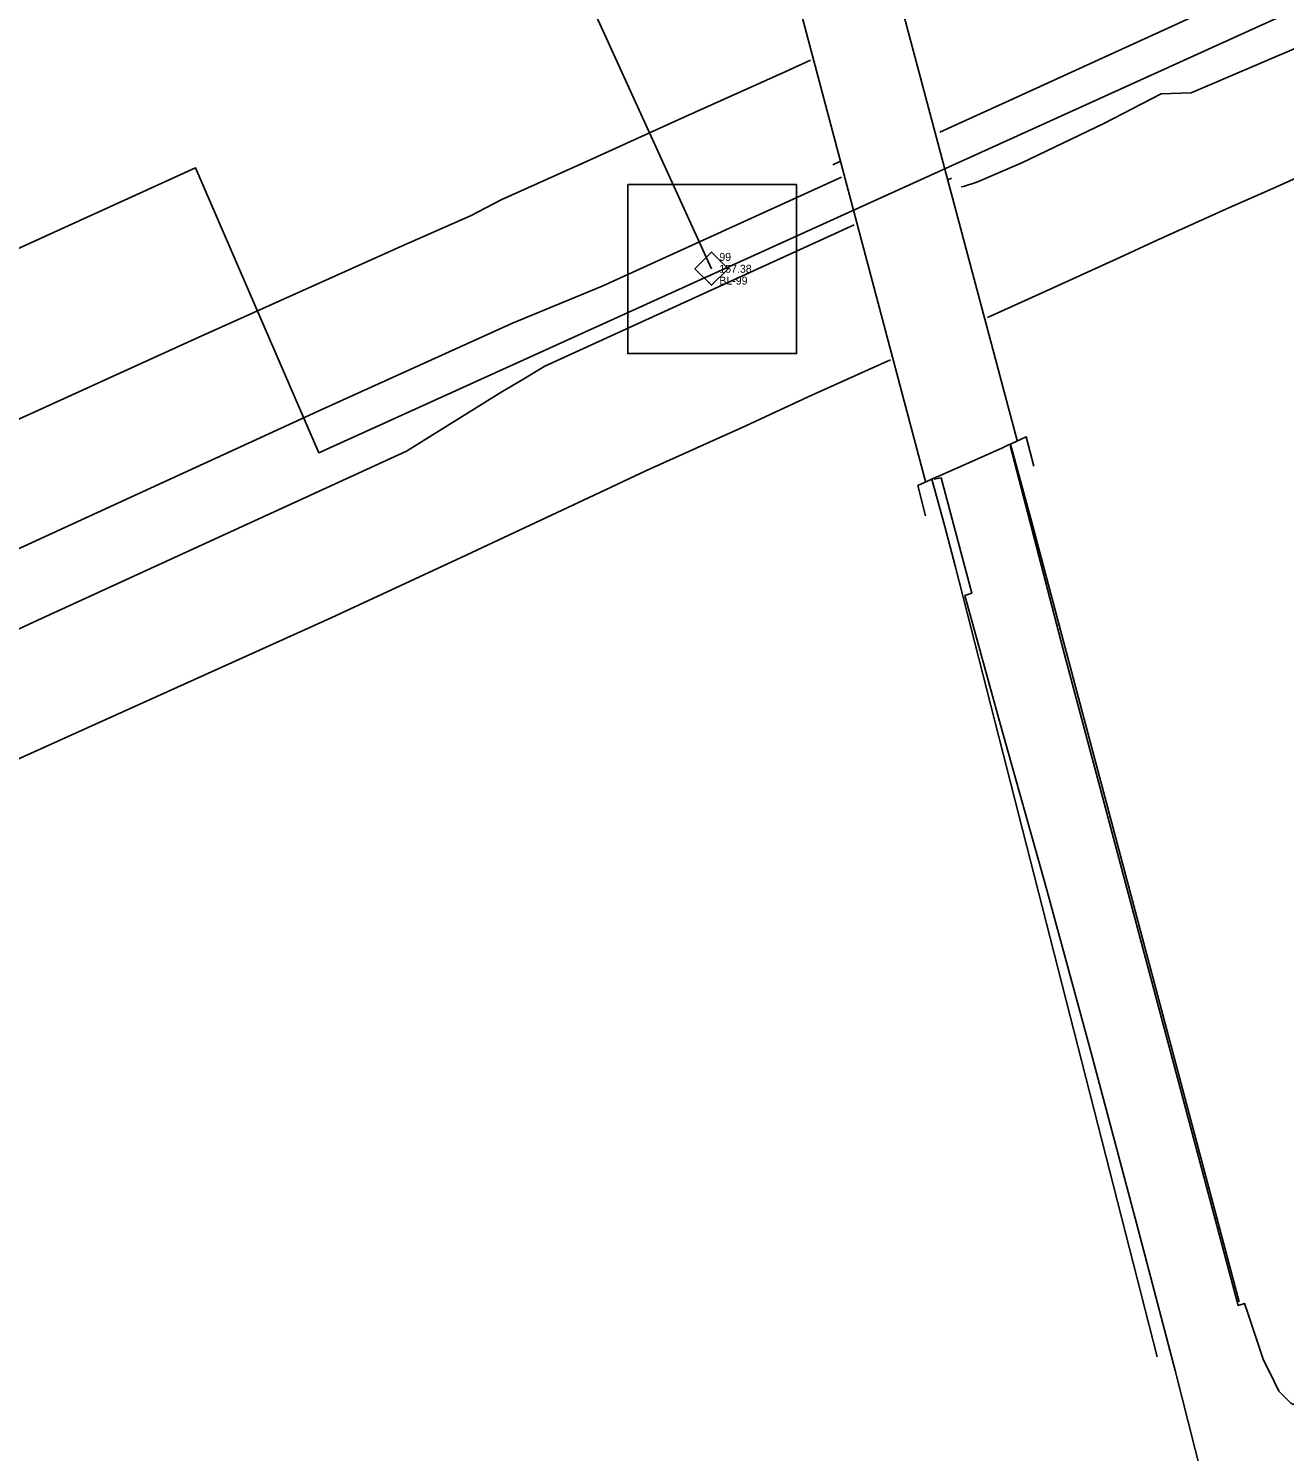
# Model space of a CAD drawing. Extents: x 2243531 to 2252747, y 658714 to 667210.
# Drawn here: x 2247409 to 2247806.2, y 662389.2 to 662839.2 of the extents above; entities that cross this region are included whole.
import ezdxf

# ---------------------------------------------------------------- set-up
doc = ezdxf.new("R2010")
doc.units = 0
for name, color, linetype in [('CTL NGS Horizontal CELL', 7, 'Continuous'), ('CTL Supplemental Horizontal and Vertical CELL', 7, 'Continuous'), ('CTL Supplemental Horizontal and Vertical Cogo Comment', 7, 'Continuous'), ('CTL Supplemental Horizontal and Vertical Cogo Elevation', 7, 'Continuous'), ('CTL Supplemental Horizontal and Vertical Cogo Number', 7, 'Continuous'), ('Exist Guardrail', 7, 'Continuous'), ('Exist Roads Curbs', 7, 'Continuous'), ('Exist Roads EOP', 7, 'Continuous'), ('Exist Roads EOP Text', 7, 'Continuous'), ('Exist Roads EOT', 7, 'Continuous'), ('Exist Structure Major Bridge WW', 7, 'Continuous'), ('Exist Structure Major Deck Tunnel Box Culvert', 7, 'Continuous'), ('Prop Horizontal Alignment', 7, 'Continuous')]:
    doc.layers.add(name, color=color, linetype=linetype)

msp = doc.modelspace()

# ---------------------------------------------------------------- linework, layer by layer
at = {"layer": 'CTL NGS Horizontal CELL'}
msp.add_line((2247624.95, 662763.25), (2247416.43, 663220.85), dxfattribs=at)
at = {"layer": 'CTL Supplemental Horizontal and Vertical CELL'}
msp.add_line((2247624.95, 662763.25), (2247624.95, 662763.25), dxfattribs=at)
msp.add_line((2247624.95, 662763.25), (2247624.95, 662763.25), dxfattribs=at)
msp.add_line((2247624.95, 662763.25), (2247624.95, 662763.25), dxfattribs=at)
for points in [[(2247598.49, 662789.89), (2247651.86, 662789.89), (2247651.86, 662736.43), (2247598.49, 662736.43)], [(2247619.74, 662763.27), (2247624.98, 662768.51), (2247630.23, 662763.26), (2247624.99, 662758.02)], [(2247619.74, 662763.27), (2247624.98, 662768.51), (2247630.23, 662763.26), (2247624.99, 662758.02)]]:
    msp.add_lwpolyline(points, close=True, dxfattribs=at)
at = {"layer": 'Exist Guardrail'}
msp.add_lwpolyline([(2247699.71, 662791.34), (2247700.84, 662791.88)], dxfattribs=at)
at = {"layer": 'Exist Roads Curbs'}
for points in [[(2247791.83, 662436.54), (2247726.17, 662683.39), (2247723.34, 662693.89), (2247719.55, 662707.82)], [(2247694.62, 662696.72), (2247698.75, 662681.72), (2247701.99, 662669.34), (2247765.92, 662419.16)]]:
    msp.add_lwpolyline(points, dxfattribs=at)
at = {"layer": 'Exist Roads EOP'}
for points in [[(2247806.05, 662855.64), (2247778.96, 662843.76), (2247718.06, 662815.97), (2247697.14, 662806.43)], [(2247703.93, 662789.15), (2247704.62, 662789.23), (2247708.87, 662790.59), (2247723.15, 662796.8), (2247748.98, 662809.19), (2247767.16, 662818.57), (2247776.69, 662818.9), (2247809.98, 662833.15), (2247815.2, 662835.56)], [(2247054.6, 662555.56), (2247231.92, 662636.42), (2247256.81, 662647.61), (2247270.03, 662654.07), (2247294.74, 662665.33), (2247312.89, 662673.14), (2247370.71, 662699.63), (2247462.68, 662741.48), (2247526.74, 662770.33), (2247548.74, 662779.98), (2247558.72, 662785.13), (2247584.29, 662796.65), (2247616.72, 662811.43), (2247648.44, 662825.64), (2247656.33, 662829.21)], [(2247712.22, 662747.88), (2247713.15, 662748.29), (2247727.42, 662754.69), (2247754.26, 662766.91), (2247764.74, 662771.77), (2247788.77, 662782.68), (2247801.57, 662788.25), (2247814.14, 662793.92), (2247830.73, 662801.46)], [(2247666.08, 662792.27), (2247590.39, 662757.78), (2247562.04, 662746.09), (2247501.78, 662718.75), (2247322.35, 662636.42), (2247244.99, 662600.89), (2247126.1, 662547.24), (2247086.01, 662529.26), (2246982.93, 662482.54)], [(2247032.55, 662479.37), (2247081.55, 662501.96), (2247160.98, 662538.21), (2247262.65, 662583.92), (2247309.79, 662604.77), (2247411.99, 662652.18), (2247528.57, 662705.59), (2247558.19, 662724), (2247564.57, 662727.86), (2247572.25, 662732.46), (2247670.09, 662777.14)], [(2247057.66, 662450.29), (2247097.63, 662468.07), (2247182.35, 662506.07), (2247205.91, 662517.28), (2247253.96, 662539.19), (2247279.59, 662550.8), (2247291.91, 662556.49), (2247301.85, 662560.92), (2247312.95, 662565.98), (2247315.25, 662567.07), (2247326.95, 662572.34), (2247340.2, 662578.53), (2247367.56, 662590.76), (2247407.57, 662608.99), (2247504.73, 662652.82), (2247545.83, 662672), (2247589.69, 662692.48), (2247604.47, 662699.41), (2247635.87, 662713.59), (2247655.54, 662722.71), (2247674.51, 662731.32), (2247681.59, 662734.43)], [(2247802.97, 662411.14), (2247799.43, 662418.42), (2247794.51, 662432.98), (2247793.49, 662436.06), (2247791.55, 662435.44), (2247736.17, 662642.9), (2247719.37, 662707.36)], [(2247781.93, 662374.05), (2247771.6, 662414.87), (2247759.38, 662461.5), (2247745.02, 662515.32), (2247730.82, 662567.55), (2247716.32, 662619.01), (2247705.11, 662659.94), (2247707.31, 662660.62), (2247697.65, 662697.11), (2247695.36, 662696.7)], [(2247849.52, 662404.52), (2247844.12, 662401.87), (2247832.33, 662399.25), (2247823.4, 662398.99), (2247815.41, 662401.25), (2247808.16, 662404.51), (2247804.34, 662408.28), (2247802.97, 662411.14)]]:
    msp.add_lwpolyline(points, dxfattribs=at)
at = {"layer": 'Exist Roads EOP Text'}
msp.add_lwpolyline([(2247117.43, 662638.28), (2247461.85, 662795.22), (2247500.8, 662705.02)], dxfattribs=at)
at = {"layer": 'Exist Roads EOT'}
msp.add_lwpolyline([(2247663.31, 662796.11), (2247665.79, 662797.25)], dxfattribs=at)
msp.add_lwpolyline([(2247663.31, 662796.11), (2247665.79, 662797.25)], dxfattribs=at)
at = {"layer": 'Exist Structure Major Bridge WW'}
msp.add_lwpolyline([(2247692.64, 662685.08), (2247690.23, 662694.77), (2247694.62, 662696.72), (2247695.11, 662696.94), (2247697.32, 662697.93), (2247707.25, 662702.35), (2247716.98, 662706.68), (2247719.13, 662707.64), (2247719.55, 662707.82), (2247719.75, 662707.92), (2247724.47, 662710.13), (2247726.91, 662700.82)], dxfattribs=at)
at = {"layer": 'Exist Structure Major Deck Tunnel Box Culvert'}
for points in [[(2247675.67, 662881.54), (2247721.67, 662708.9)], [(2247692.64, 662696), (2247646.91, 662868.42)]]:
    msp.add_lwpolyline(points, dxfattribs=at)
at = {"layer": 'Prop Horizontal Alignment'}
msp.add_line((2247500.8, 662705.02), (2249793.08, 663746.29), dxfattribs=at)

# ---------------------------------------------------------------- texts
at = {"layer": 'CTL Supplemental Horizontal and Vertical Cogo Comment'}
msp.add_text('BL-99', height=2.5, dxfattribs=at).set_placement((2247627.45, 662758.25))
msp.add_text('BL-99', height=2.5, dxfattribs=at).set_placement((2247627.45, 662758.25))
at = {"layer": 'CTL Supplemental Horizontal and Vertical Cogo Elevation'}
msp.add_text('157.38', height=2.5, dxfattribs=at).set_placement((2247627.45, 662762))
msp.add_text('157.38', height=2.5, dxfattribs=at).set_placement((2247627.45, 662762))
at = {"layer": 'CTL Supplemental Horizontal and Vertical Cogo Number'}
msp.add_text('99', height=2.5, dxfattribs=at).set_placement((2247627.45, 662765.75))
msp.add_text('99', height=2.5, dxfattribs=at).set_placement((2247627.45, 662765.75))

doc.saveas('drawing.dxf')
